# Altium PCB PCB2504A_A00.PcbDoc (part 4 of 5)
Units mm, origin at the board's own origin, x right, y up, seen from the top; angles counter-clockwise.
Board outline 115 x 60 mm, 6 copper layers (Top Layer, Signal Layer 2, Signal Layer 3, Signal Layer 4, Signal Layer 5, Bottom Layer), stack 1.555 mm thick; 403 components, 294 nets, 1344 pads, 774 vias.
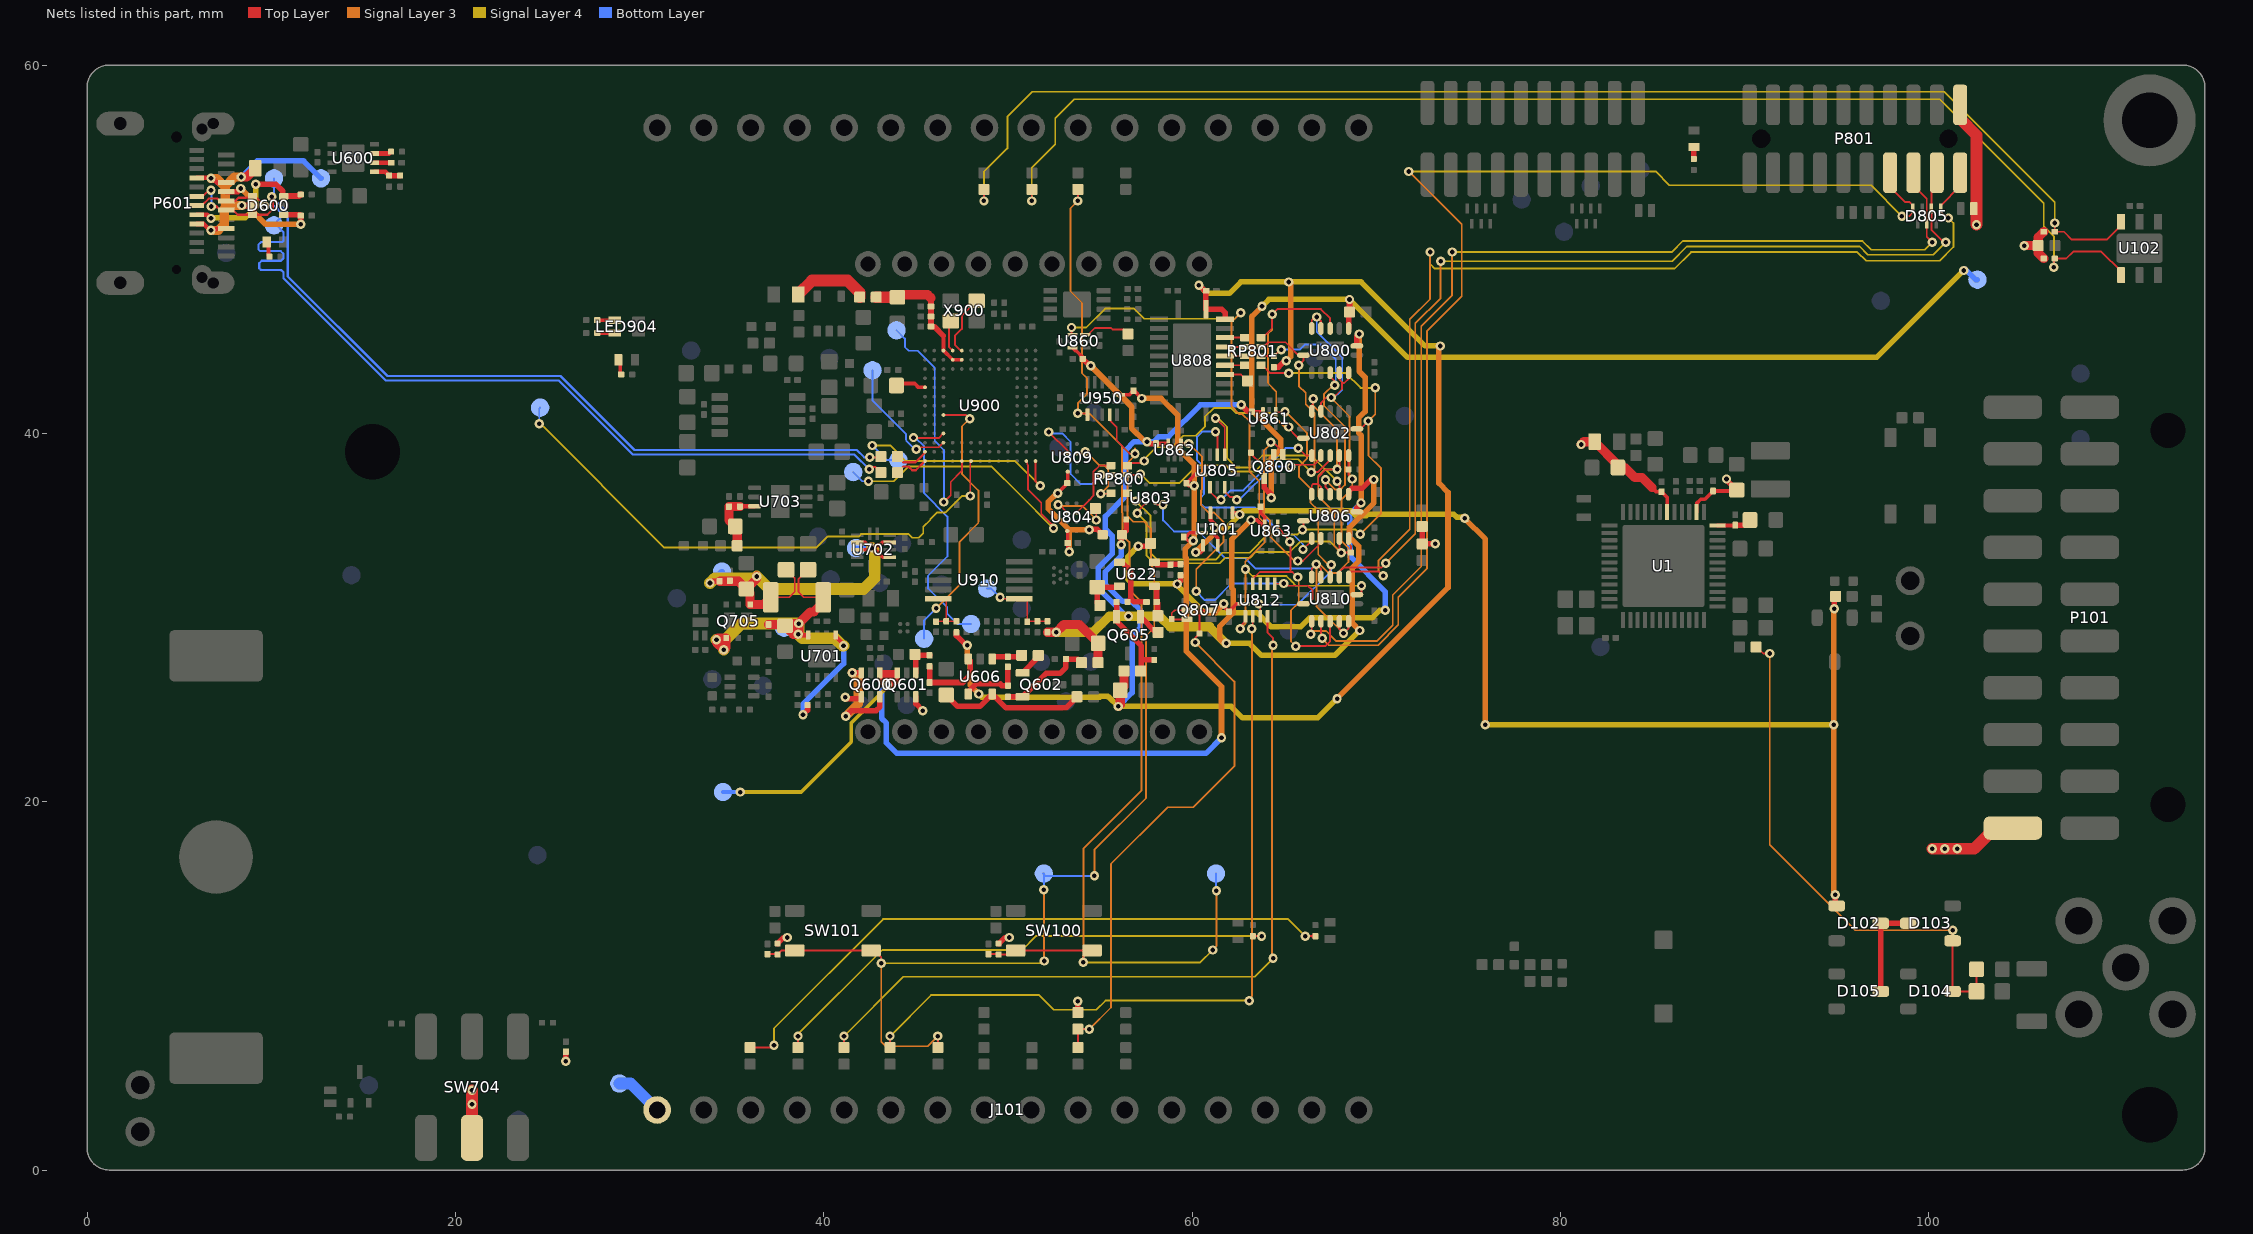
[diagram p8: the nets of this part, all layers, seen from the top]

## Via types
v1: diameter 0.508, hole 0.25, Top Layer to Bottom Layer, tented both sides, 774 vias

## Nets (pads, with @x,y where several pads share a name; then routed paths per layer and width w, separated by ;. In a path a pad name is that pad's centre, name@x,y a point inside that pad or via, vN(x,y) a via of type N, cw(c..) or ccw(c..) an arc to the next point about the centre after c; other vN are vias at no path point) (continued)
N16846192: R808.2 U802.6 U802.12 U803.C1 U806.5 U806.6 U806.12 U806.13 | length 31.6
  Top Layer w0.1: v1(57.025,35.675) 57.025,35.75 U803.C1@57.5,36.225 ; U806.6@66.5,36.7 66.5,37.175 66.575,37.25 66.85,37.25 ; U802.6@66.5,41.2 66.5,41.475 66.475,41.5 66.575,41.6 v1(66.575,41.875) ; U806.5@67,36.7 67,37.1 66.85,37.25 ; v1@68,33.6 U806.12@68,34.3 ; U802.12@68,38.8 68,38.175 v1(67.875,38.05) 67.269,38.05 66.85,37.631 66.85,37.25 ; v1(68.1,33.525) R808.2@68.625,33.525 68.625,33.9 68.5,34.025 U806.13@68.5,34.3
  Signal Layer 3 w0.1: v1(66.575,41.875) 66.575,41.5 67.875,40.2 v1(67.875,38.05) 67.2,38.05 66.85,37.7 66.85,36.6 67.725,35.725 67.725,33.9 v1(68.1,33.525)
  Signal Layer 4 w0.1: v1(57.025,35.675) 57.525,35.175 57.525,33.375 57.95,32.95 61.5,32.95 61.8,33.25 63.15,33.25 63.463,33.563 65.313,33.563 65.875,34.125 67.5,34.125 v1(68.1,33.525)
N16846231: C804.1 C810.1 L801.2 U804.A2 U809.A2 | length 8.5
  Top Layer w0.2: v1(52.7,36.75) 53.225,37.275 C810.1@53.225,37.3 53.25,37.325 U809.A2@53.25,37.925 ; U804.A2@53.225,34.7 53.25,34.675 C804.1@53.25,34.05 53.25,33.65 v1(53.325,33.575)
  Top Layer w0.3: v1(54.428,34.777) 54.404,34.8 54.85,34.8 L801.2@55.15,34.5
  Signal Layer 3 w0.3: v1(52.7,36.75) 52.653,36.75 52.2,36.297 52.2,35.902 53.325,34.777 ; v1(53.325,33.575) 53.325,34.777 ; v1(54.428,34.777) 53.325,34.777
N16846319: Q800.1 U806.10 | length 10.4
  Top Layer w0.1: v1(64.275,39.525) 64.4,39.525 64.925,39 Q800.1@64.925,38.85 ; v1(65.75,33.075) 66.025,33.075 67,34.05 U806.10@67,34.3
  Signal Layer 3 w0.1: v1(64.275,39.525) 64.275,39.425 63.9,39.05 63.9,35.6 64.237,35.262 64.237,34.588 64.237,34.393 65.556,33.075 v1(65.75,33.075)
N16846537: RP801.5 U808.21 | length 1.1
  Top Layer w0.1: U808.21@61.795,45.2 RP801.5@62.85,45.2
N16846539: RP801.6 U808.20 | length 1.1
  Top Layer w0.1: U808.20@61.795,44.7 RP801.6@62.85,44.7
N16846547: RP801.7 U808.19 | length 1.1
  Top Layer w0.1: U808.19@61.795,44.2 RP801.7@62.85,44.2
N16846551: RP801.8 U808.18 | length 1.1
  Top Layer w0.1: U808.18@61.795,43.7 RP801.8@62.85,43.7
N16846567: Q800.2 R815.1 | length 1.8
  Top Layer w0.1: R815.1@63.2,38.95 63.2,38.9 63.75,38.35 64.1,38.35 64.425,38.675 Q800.2@64.425,38.85
N16846723: R805.1 U808.17 | length 1.3
  Top Layer w0.1: U808.17@61.795,43.2 62.65,43.2 R805.1@63,42.85
N16846896: RP800.8 U809.C1 | length 4.1
  Top Layer w0.1: U809.C1@53.75,38.925 v1@54.175,38.925 ; v1(55.05,36.725) 55.575,36.725 RP800.8@55.6,36.75
  Signal Layer 3 w0.1: v1(54.2,39) 54.237,39 54.328,38.909 54.987,38.25 55.25,38.25 55.45,38.05 55.45,37.125 v1(55.05,36.725)
N16846900: RP800.6 U809.C2 | length 7.6
  Top Layer w0.1: v1(52.225,40.075) 53.25,39.05 U809.C2@53.25,38.925 ; v1(55.053,37.752) 54.952,37.752 54.95,37.75 55,37.75 RP800.6@55.6,37.75
  Bottom Layer w0.1: v1(52.225,40.075) 52.301,39.999 52.951,39.999 53.4,39.55 53.4,39.524 53.403,39.521 53.403,38.982 53.4,38.979 53.4,37.8 53.95,37.25 54.551,37.25 v1(55.053,37.752)
N16846924: RP800.5 U804.C1 | length 3.7
  Top Layer w0.1: U804.C1@53.725,35.7 54.407,36.382 54.413,36.382 54.643,36.612 54.643,36.618 54.643,37.918 54.975,38.25 RP800.5@55.6,38.25
N16847739: U805.10 U806.9 | length 13.8
  Top Layer w0.1: v1(61.275,40.1) 61.375,40 U805.10@61.375,38.855 ; v1(66.025,33.7) 66.5,34.175 U806.9@66.5,34.3
  Bottom Layer w0.1: v1(61.275,40.1) 60.55,40.1 60.275,39.825 60.275,38.55 60.65,38.175 60.65,36.7 60.492,36.542 60.492,36.169 60.675,35.986 61.139,35.986 62.43,35.986 62.437,35.993 62.763,35.993 62.77,35.986 63.414,35.986 64.882,34.518 65.482,34.518 66.025,33.975 v1(66.025,33.7)
N16847741: U805.9 U806.3 | length 12.5
  Top Layer w0.1: v1(61.275,40.825) 61.775,40.325 U805.9@61.775,38.855 ; v1(67.875,37.4) 68,37.275 U806.3@68,36.7
  Signal Layer 4 w0.1: v1(61.275,40.825) 61.425,40.825 61.9,40.35 61.9,38.65 62.4,38.15 63.175,38.15 63.825,38.8 66.481,38.8 67.875,37.406 v1(67.875,37.4)
N16847743: U802.10 U805.4 | length 6.7
  Top Layer w0.1: U805.4@61.775,37.085 61.775,36.825 62.05,36.55 62.275,36.55 v1(62.425,36.4) ; v1(65.375,38.2) 65.475,38.3 66.376,38.3 66.624,38.3 67,38.676 U802.10@67,38.8
  Bottom Layer w0.1: v1(62.425,36.4) 62.575,36.4 64.375,38.2 v1(65.375,38.2)
N16847749: U802.9 U805.2 | length 7.5
  Top Layer w0.1: U805.2@60.975,37.085 60.975,36.845 61.395,36.425 61.575,36.425 v1(61.575,36.391) ; v1@65.6,39.2 v1(65.775,39.2) 66.175,38.8 U802.9@66.5,38.8
  Bottom Layer w0.1: v1(61.575,36.391) 62.091,36.907 62.788,36.907 65.081,39.2 v1(65.775,39.2)
N16847975: R810.1 U804.C2 | length 3.8
  Top Layer w0.1: v1(52.725,36.125) 52.725,36.15 52.75,36.175 U804.C2@53.225,35.7 ; R810.1@54.75,35.925 54.8,35.875 v1(54.8,35.3)
  Signal Layer 3 w0.1: v1(52.725,36.125) 52.8,36.05 54.075,36.05 54.825,35.3 v1(54.8,35.3)
N16851386: C127.2 D103.1 D104.3 R128.2 R129.1 | length 28.9
  Top Layer w0.1: R129.1@90.675,28.4 91.025,28.05 v1(91.375,28.05) ; v1(101.3,13.025) D103.1@101.3,12.45 D104.3@101.3,9.7 R128.2@102.6,9.7 C127.2@102.6,10.9
  Signal Layer 3 w0.1: v1(91.375,28.05) 91.375,17.675 96.025,13.025 v1(101.3,13.025)
N16870930: D102.3 D103.3 D105.3 | length 5.2
  Top Layer w0.3: D105.3@97.4,9.7 D102.3@97.4,13.4 D103.3@98.9,13.4
N16916520: U810.1 U812.1 U860.4 | length 37.3
  Top Layer w0.1: v1(53.453,45.752) 53.453,45.397 U860.4@53.5,45.35 ; v1(62.625,29.4) 62.625,29.525 62.9,29.8 U812.1@62.9,30.065 ; U810.1@68.95,31.25 68.975,31.275 69.15,31.275 69.2,31.325 v1(69.2,31.725)
  Signal Layer 3 w0.1: v1(62.625,29.4) 62.9,29.675 v1(62.9,32.625) 62.887,32.637 62.887,33.038 63.95,34.1 63.95,35.125 63.65,35.425 63.65,37.4 63.125,37.925 63.125,40.65 62.725,41.05 62.575,41.05 62.15,41.475 62.15,46.05 v1(62.65,46.55)
  Signal Layer 4 w0.1: v1(53.453,45.752) 54.252,45.752 55.275,46.775 56.85,46.775 57.4,46.225 62.325,46.225 v1(62.65,46.55) ; v1(62.9,32.625) 63.268,32.257 65.124,32.257 65.407,31.974 65.407,31.962 65.637,31.732 65.649,31.732 65.656,31.725 v1(69.2,31.725)
N16916530: U810.4 U812.3 U861.4 | length 16.8
  Top Layer w0.1: v1(63.625,30.75) 63.7,30.675 U812.3@63.7,30.065 ; U861.4@64.55,41.15 65.025,41.15 v1(65.05,41.175) ; U810.4@67.5,32.2 67.5,32.775 67.55,32.825 v1(67.55,32.875)
  Signal Layer 3 w0.1: v1(65.05,41.175) 65.081,41.175 66.25,40.006 66.25,38.65 65.8,38.2 65.8,37.642 66.425,37.017 66.425,36.25 66.85,35.825 66.85,33.425 67.4,32.875 v1(67.55,32.875)
  Bottom Layer w0.1: v1(63.625,30.75) 63.675,30.7 65.725,30.7 67.55,32.525 v1(67.55,32.875)
N16916558: U810.11 U812.11 U863.4 | length 13
  Top Layer w0.1: U812.11@63.3,31.835 63.3,32.1 63.675,32.475 65.343,32.475 ; U863.4@64.65,35.05 64.65,34.925 64.9,34.675 64.9,34.6 65.3,34.2 v1(65.3,34.125) 65.343,34.082 65.343,32.475 ; v1(65.625,28.45) 67.225,28.45 67.5,28.725 U810.11@67.5,29.8 ; v1(65.75,32.2) 65.725,32.2 65.45,32.475 65.343,32.475
  Signal Layer 3 w0.1: v1(65.625,28.45) 65.375,28.7 65.375,30.389 65.793,30.807 65.793,32.118 65.75,32.161 v1(65.75,32.2)
N16916616: U810.8 U812.8 U862.4 | length 18.7
  Top Layer w0.1: U862.4@59.4,39.45 v1(59.825,39.45) ; U812.8@64.5,31.835 64.96,31.835 v1(64.975,31.85) 65.093,31.732 66.293,31.732 66.55,31.475 66.55,31.025 66.275,30.75 U810.8@66.05,30.75
  Signal Layer 3 w0.1: v1(59.825,39.45) 60.55,38.725 60.55,36.975 60.492,36.917 60.492,36.108 60.9,35.7 61.2,35.7 61.7,35.2 61.7,34.1 60.225,32.625 v1(60.225,31.425)
  Bottom Layer w0.1: v1(60.225,31.425) 60.7,30.95 61.225,30.95 62.125,31.85 v1(64.975,31.85)
N16917071: R882.1 U860.3 | length 2.6
  Top Layer w0.1: U860.3@54.2,45.35 54.35,45.35 54.725,45.725 55.612,45.725 55.687,45.65 56.275,45.65 R882.1@56.525,45.4
N16922979: R601.1 R602.2 U600.5 | length 1.5
  Top Layer w0.25: U600.5@15.6,54.2 16.2,54.2 R601.1@16.4,54
  Top Layer w0.3: R601.1@16.4,54 R602.2@17,54
N16923003: R600.1 U600.7 | length 0.9
  Top Layer w0.25: U600.7@15.6,55.2 16.4,55.2 R600.1@16.5,55.3
N16923019: C602.1 U600.6 | length 0.9
  Top Layer w0.25: U600.6@15.6,54.7 C602.1@16.525,54.7
N16923678: C620.1 R682.2 U606.4 | length 3.5
  Top Layer w0.3: U606.4@47.85,25.85 47.85,25.975 48.275,26.4 49.575,26.4 49.675,26.3 R682.2@50,26.3 C620.1@50,27.325
N16923728: Q601.4 R628.1 R672.2 | length 1.8
  Top Layer w0.3: R628.1@44.95,28 R628.1@45,27.95 ; Q601.4@45,27 R628.1@45,27.95 ; R672.2@45.75,27.95 R628.1@45,27.95
N16923751: C654.1 R689.2 U622.4 | length 3.5
  Top Layer w0.3: U622.4@56.05,33 56.2,33 56.675,32.525 56.675,31.025 ; R689.2@56.5,30.85 56.675,31.025 ; C654.1@57.525,30.85 56.85,30.85 56.675,31.025
N16923761: Q605.1 R686.2 | length 1.3
  Top Layer w0.3: Q605.1@57.2,30.05 58.05,29.2 R686.2@58.15,29.2
N16923771: C653.1 R629.1 U622.3 | length 1.5
  Top Layer w0.3: U622.3@57.95,33 58.075,32.875 C653.1@58.825,32.875 58.85,32.9 R629.1@59.375,32.9
N16923785: Q605.2 R687.1 R688.1 R689.1 | length 5.1
  Top Layer w0.3: R689.1@55.9,30.85 Q605.2@55.9,30.05 55.9,29.803 57.25,28.453 57.25,27.75 ; R687.1@57.2,27.1 57.25,27.15 57.25,27.75 ; R688.1@57.95,27.7 57.3,27.7 57.25,27.75
N16923803: C654.2 R686.1 U622.1 | length 1.7
  Top Layer w0.3: U622.1@57.95,31.7 58.075,31.575 C654.2@58.075,30.85 58.15,30.775 R686.1@58.15,30.1
N16923899: C652.1 R690.1 U622.5 | length 2.3
  Top Layer w0.3: R690.1@55,30.65 54.85,30.8 C652.1@54.85,31.65 56,31.65 U622.5@56.05,31.7
N16923917: C660.1 R681.1 U606.5 | length 8.2
  Top Layer w0.3: C660.1@46.65,25.8 47.275,25.175 48.475,25.175 U606.5@49.15,25.85 49.9,25.1 53.15,25.1 R681.1@53.75,25.7
N16923949: Q602.1 R679.2 | length 1.3
  Top Layer w0.3: Q602.1@50.8,27 51.65,27.85 R679.2@51.65,27.95
N16923963: C621.1 R672.1 U606.3 | length 4.2
  Top Layer w0.3: R672.1@45.75,27.35 C621.1@45.75,26.475 47.55,26.475 47.95,26.875 47.95,27.65 U606.3@47.85,27.75
N16923985: Q602.2 R674.1 R675.1 R682.1 | length 5.2
  Top Layer w0.3: R682.1@50,25.7 Q602.2@50.8,25.7 52.075,26.975 52.825,26.975 53.15,27.3 R674.1@53.15,27.75 53.8,27.75 R675.1@54,27.55
N16924018: C620.2 R679.1 U606.1 | length 1.7
  Top Layer w0.3: U606.1@49.15,27.75 49.275,27.875 C620.2@50,27.875 50.675,27.875 R679.1@50.75,27.95
N16924927: Q600.3 Q600.6 | length 5.9
  Top Layer w0.3: v1(41.2,24.65) 41.5,24.95 42.85,24.95 43.05,25.15 Q600.3@43.05,25.7 ; v1(41.55,27) Q600.6@42.05,27
  Signal Layer 3 w0.5: v1(41.2,24.65) 41.875,25.325 41.875,26.675 v1(41.55,27)
N16934878: C900.1 U900.J13 | length 1.7
  Top Layer w0.2: C900.1@43.95,42.6 44.057,42.707 44.939,42.707 45.146,42.5 U900.J13@45.5,42.5
N16934900: C903.1 C904.1 C905.1 C906.1 R130.2 U900.M9 U900.M10 U900.N11 | length 7.5
  Top Layer w0.2: 46.5,45.3 U900.N11@46.5,44.5 U900.M10@47,44 U900.M9@47.5,44
  Top Layer w0.3: 45.825,47.35 C906.1@45.825,46.9 C905.1@45.825,46.35 C904.1@45.825,45.8 46,45.8 46.5,45.3
  Top Layer w0.5: C903.1@44,47.4 44.125,47.525 45.65,47.525 45.825,47.35
  Top Layer w0.635: R130.2@42.85,47.4 C903.1@44,47.4
N16936696: U900.N10 X900.1 | length 1.7
  Top Layer w0.1: X900.1@46.9,46.1 46.8,46 46.8,44.7 U900.N10@47,44.5
N16936699: U900.N9 X900.3 | length 3.4
  Top Layer w0.1: U900.N9@47.5,44.5 47.45,44.5 47.125,44.825 47.125,45.3 47.5,45.675 47.5,46.4 X900.3@48.3,47.2
N16939106: TPJ909.1 U900.C11 | length 6.7
  Top Layer w0.1: v1@45.25,39.25 46.25,39.25 U900.C11@46.5,39.5
  Bottom Layer w0.1: TPJ909.1@42.651,43.427 42.651,41.774 44.475,39.95 44.475,39.656 44.482,39.649 44.482,39.612 44.944,39.15 v1(45.025,39.15)
N16939109: TPJ910.1 U900.D11 | length 14.5
  Top Layer w0.1: v1(44.875,39.775) 44.9,39.75 46.25,39.75 U900.D11@46.5,40
  Bottom Layer w0.1: v1(44.875,39.775) 44.975,39.775 45.45,39.3 45.45,36.75 46.718,35.482 46.718,33.318 45.662,32.263 45.662,31.588 46.7,30.55 46.7,30.2 47.25,29.65 TPJ910.1@48.003,29.65
N16939489: TPJ911.1 U900.F11 | length 15.2
  Top Layer w0.1: U900.F11@46.5,41 47.725,41 v1(47.925,40.8)
  Signal Layer 3 w0.1: v1(46.1,30.5) 47.375,31.775 47.375,34.119 48.393,35.137 48.393,35.193 48.4,35.2 48.4,36.9 47.5,37.8 47.5,40.375 v1(47.925,40.8)
  Bottom Layer w0.1: TPJ911.1@45.453,28.85 45.453,29.853 v1(46.1,30.5)
N16939638: TPJ900.1 U900.A2 | length 17.1
  Top Layer w0.1: U900.A2@51,38.5 51.05,38.45 51.05,38.314 51.1,38.264 51.1,36.954 51.81,36.243 51.81,35.64 52.475,34.975 v1(52.475,34.85)
  Signal Layer 4 w0.1: v1(42.429,37.4) 43.8,37.4 44.6,38.2 49.125,38.2 50.55,36.775 v1(52.475,34.85)
  Bottom Layer w0.1: TPJ900.1@41.602,37.9 42.102,37.4 v1(42.429,37.4)
N16939640: TPJ901.1 U900.A1 | length 13.6
  Top Layer w0.1: U900.A1@51.5,38.5 51.5,37.375 51.737,37.137 51.8,37.075 51.875,37.15 v1(51.75,37.15)
  Signal Layer 4 w0.1: v1(42.631,39.346) 43.604,39.346 44.45,38.5 50.4,38.5 v1(51.75,37.15)
  Bottom Layer w0.1: v1(42.631,39.346) 43.426,38.55 TPJ901.1@44.053,38.55
N16940103: TPJ908.1 U900.A9 | length 13.3
  Top Layer w0.1: v1(46.525,36.275) 46.9,36.65 46.9,37.362 47.5,37.962 U900.A9@47.5,38.5
  Bottom Layer w0.1: TPJ908.1@43.952,45.601 44.407,45.146 44.407,44.693 44.607,44.493 45.107,44.493 46.025,43.575 46.025,39.6 46.525,39.1 v1(46.525,36.275)
N16942491: R902.2 U900.B13 | length 1.9
  Top Layer w0.12: R902.2@44,38.75 44.32,38.43 44.98,38.43 45.5,38.95 U900.B13@45.5,39
N16942503: R904.2 U900.A13 | length 1.9
  Top Layer w0.12: R904.2@44,37.875 44.325,38.2 44.6,38.2 44.8,38 45,38 U900.A13@45.5,38.5
N16943456: TPJ902.1 U900.A8 | length 30.7
  Top Layer w0.1: v1(47.95,36.6) 47.957,36.607 47.957,38.457 U900.A8@48,38.5
  Signal Layer 4 w0.1: v1(24.551,40.527) v1(24.551,40.527) 24.55,40.6 31.35,33.8 39.6,33.8 40.2,34.4 41.9,34.4 42.032,34.532 44.468,34.532 ; 44.513,34.532 44.468,34.532 ; v1(47.95,36.6) 47.5,36.6 46.6,35.7 46.144,35.7 45.782,35.338 45.782,35.3 45.407,34.925 45.407,34.571 45.168,34.332 44.812,34.332 44.612,34.532 44.468,34.532
  Bottom Layer w0.1: v1(24.551,40.527) 24.551,41.351 TPJ902.1@24.6,41.4
N16944010: LED903.2 R912.2 | length 0.9
  Top Layer w0.2: LED903.2@28.85,44 28.95,43.9 28.95,43.25 R912.2@29,43.2
N16966205: LED904.2 R920.2 | length 0.9
  Top Layer w0.2: R920.2@27.7,46.15 LED904.2@28.65,46.15
N16966207: LED904.1 R919.2 | length 0.9
  Top Layer w0.2: R919.2@27.7,45.45 LED904.1@28.65,45.45
N16966211: LED901.1 R903.2 | length 0.9
  Top Layer w0.2: LED901.1@9.75,50.4 9.85,50.3 9.85,49.65 R903.2@9.9,49.6
N16966215: LED900.1 R900.2 | length 0.7
  Top Layer w0.3: R900.2@87.25,54.9 LED900.1@87.25,55.55
N16996446: Q807.5 Q807.6 R838.1 | length 2
  Top Layer w0.1: Q807.6@59.725,29.9 58.925,29.9 R838.1@58.9,29.925 58.9,30.25 59.05,30.4 Q807.5@59.725,30.4
N17012885: L900.2 R130.1 | length 4.2
  Top Layer w0.635: L900.2@38.615,47.55 39.365,48.3 41.3,48.3 41.95,47.65 R130.1@41.95,47.4
N17065843: C15.1 C16.1 U1.36 | length 1.9
  Top Layer w0.2: U1.36@88.535,35 89.475,35 C15.1@89.5,35.025
  Top Layer w0.3: C15.1@89.5,35.025 90.025,35.025 C16.1@90.3,35.3
SENSOR_I2C_SCL: R109.2 R303.2 U102.6 | length 71.5
  Top Layer w0.1: v1(48.7,52.625) R303.2@48.7,53.25 ; v1(106.85,51.425) R109.2@106.85,50.95 107.35,50.95 107.775,50.525 109.675,50.525 110.45,51.3 U102.6@110.45,51.5
  Signal Layer 4 w0.1: v1(48.7,52.625) 48.7,54.2 49.975,55.475 49.975,57.2 51.325,58.55 100.85,58.55 106.85,52.55 v1(106.85,51.425)
SENSOR_I2C_SDA: R108.2 R302.2 U102.1 | length 70.7
  Top Layer w0.1: v1(51.3,52.625) R302.2@51.3,53.25 ; v1(106.8,49.025) 106.8,49.45 R108.2@106.85,49.5 107.475,49.5 107.85,49.875 109.375,49.875 110.45,48.8 U102.1@110.45,48.6
  Signal Layer 4 w0.1: v1(51.3,52.625) 51.3,54.425 52.575,55.7 52.575,57.125 53.6,58.15 100.6,58.15 106.25,52.5 106.25,51.25 106.8,50.7 v1(106.8,49.025)
SI_HEADER_ENABLE: R807.2 U800.5 U800.6 U800.12 U800.13 U802.5 U802.13 U803.C2 U810.5 U810.6 U810.12 U810.13 | length 42.2
  Top Layer w0.1: U803.C2@58,36.225 58.1,36.125 v1(58.425,36.125) ; U810.6@66.5,32.2 66.5,32.65 v1(66.75,32.9) 67,32.65 U810.5@67,32.2 ; U800.6@66.5,45.7 66.5,46.15 66.675,46.325 v1(66.775,46.325) 67,46.1 U800.5@67,45.7 ; U802.5@67,41.2 67,41.65 67.3,41.95 v1(67.55,41.95) 67.55,41.881 67.581,41.85 68.143,42.412 68.143,42.738 ; U810.12@68,29.8 68,29.375 v1(68.225,29.15) 68.5,29.425 U810.13@68.5,29.8 ; U800.12@68,43.3 68,42.931 68.143,42.788 68.143,42.738 ; U802.13@68.5,38.8 R807.2@68.5,38.05 68.5,37.725 v1(68.7,37.525) ; U800.13@68.5,43.3 68.5,42.975 68.263,42.738 68.143,42.738
  Signal Layer 3 w0.1: v1(67.55,41.95) 67.525,41.95 68.55,40.925 68.55,37.675 v1(68.7,37.525) 68.7,37 68.125,36.425 68.125,34.15 68.493,33.782 68.493,33.018 67.9,32.425 67.4,32.425 66.925,32.9 v1(66.75,32.9) 66.75,30.625 v1(68.225,29.15)
  Bottom Layer w0.1: v1(58.425,36.125) 58.425,35.275 59.025,34.675 60.35,34.675 61.8,33.225 62.9,33.225 63.462,32.663 66.513,32.663 v1(66.75,32.9) ; v1(66.775,46.325) 66.775,45.525 68.157,44.143 68.157,42.382 v1@67.625,41.85
SI_VCOM_CTS: D805.4 P801.8 U810.10 | length 64.2
  Top Layer w0.1: U810.10@67,29.8 67,28.95 v1(67.075,28.875) ; P801.8@97.905,54.158 97.905,53.37 98.7,52.575 98.95,52.575 99.15,52.375 D805.4@99.15,52.215 99.15,52 98.95,51.8 v1(98.55,51.8)
  Signal Layer 3 w0.1: v1(67.075,28.875) 67.075,28.85 67.425,28.5 70.1,28.5 71.2,29.6 71.2,31.1 72.75,32.65 72.75,45.55 74.65,47.45 74.65,51.35 v1(71.775,54.225)
  Signal Layer 4 w0.1: v1(71.775,54.225) 85.175,54.225 85.925,53.475 96.875,53.475 v1(98.55,51.8)
SI_VCOM_RTS: D805.6 P801.6 U810.9 | length 58.3
  Top Layer w0.1: v1(66.45,29.1) 66.5,29.15 U810.9@66.5,29.8 ; P801.6@99.175,54.158 99.175,53.475 99.9,52.75 D805.6@99.9,51.385 99.9,50.675 v1(100.2,50.375)
  Signal Layer 3 w0.1: v1(66.45,29.1) 66.625,29.275 67.275,29.275 67.825,28.725 70.042,28.725 70.9,29.583 70.9,31.225 72.45,32.775 72.45,45.825 74.125,47.5 v1(74.125,49.85)
  Signal Layer 4 w0.1: v1(74.125,49.85) 86.05,49.85 86.65,50.45 96.4,50.45 96.875,49.975 99.8,49.975 v1(100.2,50.375)
SI_VCOM_RXD: D805.1 P801.2 U810.2 | length 55.9
  Top Layer w0.1: U810.2@68.5,32.2 68.5,32.4 68.6,32.5 70.15,32.5 v1(70.375,32.275) ; v1(101.075,51.7) 101,51.7 100.65,52.05 D805.1@100.65,52.215 100.65,52.375 101.715,53.44 P801.2@101.715,54.158
  Signal Layer 3 w0.1: v1(70.375,32.275) 70.132,32.518 70.132,33.113 71.825,34.806 71.825,46.2 72.925,47.3 v1(72.925,49.85)
  Signal Layer 4 w0.1: v1(72.925,49.85) 72.925,49.2 73.175,48.95 86.2,48.95 87.1,49.85 96.125,49.85 96.6,49.375 100.6,49.375 101.35,50.125 101.35,51.425 v1(101.075,51.7)
SI_VCOM_TXD: D805.2 P801.4 U810.3 | length 53.1
  Top Layer w0.1: U810.3@68,32.2 68,32.475 68.238,32.713 70.288,32.713 v1(70.525,32.95) ; P801.4@100.445,54.158 100.15,53.863 D805.2@100.15,52.215 100.15,51.05 100.825,50.375 v1(100.925,50.375)
  Signal Layer 3 w0.1: v1(70.525,32.95) 72.125,34.55 72.125,45.975 73.5,47.35 v1(73.5,49.35)
  Signal Layer 4 w0.1: v1(73.5,49.35) 86.075,49.35 86.875,50.15 96.25,50.15 96.7,49.7 100.25,49.7 v1(100.925,50.375)
TCK_SWCLK: RP800.3 RP801.3 U800.8 U802.11 | length 22.5
  Top Layer w0.1: RP800.3@56.5,37.75 57.15,37.75 v1(57.2,37.8) ; RP801.3@63.75,44.7 63.889,44.7 64.139,44.95 65.075,44.95 65.775,44.25 U800.8@66.05,44.25 66.05,43.95 v1(65.803,43.702) ; v1(66.475,37.9) 66.824,37.9 67.5,38.576 U802.11@67.5,38.8
  Signal Layer 3 w0.1: v1@65.825,43.724 v1(65.803,43.702) 65.803,42.572 66.175,42.2 66.175,41.575 66.65,41.1 66.65,38.075 v1(66.475,37.9)
  Signal Layer 4 w0.1: v1@57.3,37.8 v1(57.2,37.8) 57.7,37.3 59.3,37.3 60.271,38.271 61.829,38.271 62.175,37.925 63.4,37.925 64.075,38.6 65.775,38.6 v1(66.475,37.9)
TDI: RP800.1 RP801.1 U802.1 U806.8 | length 33
  Top Layer w0.1: RP800.1@56.5,36.75 56.85,36.4 v1@56.95,36.4 ; v1(56.953,36.327) 56.95,36.33 v1@56.95,36.4 ; v1@57,36.4 v1@56.95,36.4 ; RP801.1@63.75,43.7 63.827,43.7 64.252,43.275 v1(65.25,43.275) ; v1@66.05,34.875 U806.8@66.05,35.25 ; U802.1@68.95,40.25 69.15,40.25 v1(69.575,40.675)
  Signal Layer 3 w0.1: v1(69.128,34.527) 70.268,35.666 70.268,38.107 69.575,38.8 v1(69.575,40.675) 69.95,41.05 v1(69.95,42.475)
  Signal Layer 4 w0.1: v1(56.953,36.327) 57.749,35.53 57.749,33.501 58.1,33.15 61.278,33.15 61.65,33.522 63.122,33.522 64.118,34.518 65.743,34.518 v1(66,34.775) 68.88,34.775 v1(69.128,34.527) 69.128,34.528 v1@69.2,34.6 ; v1(65.25,43.275) 68.35,43.275 69.15,42.475 v1(69.95,42.475)
TDO_SWO: R801.1 RP801.2 U800.11 U806.4 | length 15.3
  Top Layer w0.1: RP801.2@63.75,44.2 R801.1@64.45,44.2 64.775,44.525 64.825,44.525 v1(64.85,44.55) ; v1(67.25,37.475) 67.25,37.074 67.5,36.824 U806.4@67.5,36.7 ; U800.11@67.5,43.3 67.5,43.075 67.75,42.825 v1(67.75,42.625)
  Signal Layer 3 w0.1: v1(67.25,37.475) 67.25,37.469 67.769,36.95 68.05,36.95 68.3,37.2 68.3,40.375 67.157,41.518 67.157,42.126 67.656,42.625 v1(67.75,42.625)
  Bottom Layer w0.1: v1(64.85,44.55) 65.85,44.55 66.125,44.825 67,44.825 67.8,44.025 67.8,42.65 67.775,42.625 v1(67.75,42.625)
TMS_SWDIO: RP800.4 RP801.4 U800.4 U802.8 | length 24.5
  Top Layer w0.1: RP800.4@56.5,38.25 56.55,38.25 56.7,38.4 56.9,38.4 57.2,38.4 57.3,38.5 v1(57.4,38.5) ; RP801.4@63.75,45.2 63.825,45.2 64.35,45.725 v1(64.35,46.475) 64.625,46.75 67,46.75 67.5,46.25 U800.4@67.5,45.7 ; v1(65.25,40.35) 65.175,40.35 65.775,39.75 U802.8@66.05,39.75
  Signal Layer 3 w0.1: v1(64.35,46.475) 64.35,45.625 64.125,45.4 64.125,42.725 64.575,42.275 64.575,40.8 65.1,40.275 65.175,40.35 v1(65.25,40.35)
  Signal Layer 4 w0.1: v1(57.4,38.5) 57.4,38.6 58.05,39.25 58.9,39.25 59.525,39.875 60.206,39.875 60.7,40.369 60.7,40.9 61.175,41.375 62.125,41.375 62.4,41.1 64.275,41.1 65.05,40.325 65.075,40.35 v1(65.25,40.35)
UIF_BUTTON0: C102.1 R100.1 R301.2 SW100.3 SW100.4 TPJ652.1 U950.8 | length 64.4
  Top Layer w0.1: C102.1@48.95,11.725 49.475,11.725 R100.1@49.5,11.7 50.2,11.7 SW100.3@50.425,11.925 SW100.4@54.35,11.925 ; v1(53.8,41.088) 54.253,41.088 U950.8@54.325,41.015 ; v1(53.8,52.625) R301.2@53.8,53.25 ; v1(54.1,11.275) 54.1,11.675 SW100.4@54.35,11.925 ; SW100.4@54.575,11.925 SW100.4@54.35,11.925
  Signal Layer 3 w0.1: v1(53.8,52.625) 53.4,52.225 53.4,47.725 54.025,47.1 54.025,43.275 54.3,43 54.3,42.15 53.8,41.65 v1(53.8,41.088) 54.412,41.088 56.2,39.3 56.2,35.7 56.218,35.682 56.218,34.482 56.6,34.1 56.6,31.5 57.25,30.85 57.25,20.6 54.1,17.45 v1(54.1,11.275) ; v1(61.125,11.95) 61.325,12.15 v1(61.325,15.175)
  Signal Layer 4 w0.1: v1(54.1,11.275) 60.45,11.275 v1(61.125,11.95)
  Bottom Layer w0.1: TPJ652.1@61.303,16.102 61.303,15.197 v1(61.325,15.175)
UIF_BUTTON1: C103.1 R101.1 R308.2 SW101.3 SW101.4 TPJ653.1 U950.11 | length 60.1
  Top Layer w0.1: C103.1@36.95,11.725 37.475,11.725 R101.1@37.5,11.7 37.725,11.925 SW101.3@38.425,11.925 SW101.4@42.575,11.925 42.75,11.925 43.125,11.55 v1(43.125,11.225) ; R308.2@46.2,6.65 v1@46.2,7.275 ; U950.11@55.525,41.015 55.525,40.725 55.91,40.34 55.91,39.615 56.625,38.9 v1(56.9,38.9)
  Signal Layer 3 w0.1: v1(43.125,11.225) 43.125,6.975 43.375,6.725 45.65,6.725 v1(46.2,7.275) ; v1(51.953,15.226) 51.953,11.372 v1(51.975,11.35) ; v1(54.7,15.975) 54.7,17.4 57.5,20.2 57.5,29 57.95,29.45 57.95,32.65 57.769,32.831 57.769,34.831 57.4,35.2 56.8,35.2 56.5,35.5 56.5,38.4 56.9,38.8 v1(56.9,38.9) 56.9,39.189
  Signal Layer 4 w0.1: v1(43.125,11.225) 51.85,11.225 v1(51.975,11.35)
  Bottom Layer w0.1: v1(51.953,15.226) 51.95,15.228 51.95,15.275 51.953,15.278 TPJ653.1@51.953,16.051 ; v1(54.7,15.975) 52.029,15.975 TPJ653.1@51.953,16.051 ; TPJ653.1@51.953,16.051 51.902,16.102 TPJ653.1@51.953,16.102 TPJ653.1@51.953,16.051
UIF_LED0: R106.2 R314.2 | length 34.5
  Top Layer w0.1: R314.2@36,6.65 37.175,6.65 v1(37.3,6.775) ; v1(66.15,12.7) R106.2@66.65,12.7
  Top Layer w0.3: R106.2@66.65,12.7 R106.2@66.7,12.7
  Signal Layer 4 w0.1: v1(37.3,6.775) 37.3,7.7 43.225,13.625 65.225,13.625 v1(66.15,12.7)
UIF_LED1: R107.2 R315.2 | length 28.6
  Top Layer w0.1: R315.2@38.6,6.65 v1(38.6,7.275) ; R107.2@63.3,12.7 v1(63.775,12.7)
  Signal Layer 4 w0.1: v1(38.6,7.275) 38.6,7.375 43.175,11.95 50.775,11.95 51.525,12.7 v1(63.775,12.7)
USB_DM: D600.6 P601.A7 P601.B7 R902.1 TPJ612.1 | length 48.1
  Top Layer w0.12: P601.B7@5.95,52.875 6.275,52.875 6.6,53.2 v1(6.725,53.2) ; v1@6.75,52.35 7,52.35 7.225,52.125 P601.A7@7.55,52.125 7.925,52.125 8.175,51.875 D600.6@8.975,51.875 9.778,51.875 10.075,52.172 10.075,52.8 v1(10.025,52.85) ; v1(42.5,38.7) 43.05,38.7 R902.1@43.1,38.75
  Bottom Layer w0.12: v1@6.725,53.15 6.75,53.125 v1@6.75,52.35 ; TPJ612.1@10.15,53.85 10.15,52.975 v1(10.025,52.85) 10.9,51.975 10.9,48.525 16.31,43.115 25.71,43.115 27.55,41.275 29.725,39.1 41.8,39.1 42.2,38.7 v1(42.5,38.7)
  other v1: 6.75,52.325
USB_DP: D600.4 P601.A6 P601.B6 R904.1 TPJ611.1 | length 51.1
  Top Layer w0.12: P601.B6@5.95,52.375 6.225,52.375 6.6,52.75 7.075,52.75 7.2,52.625 P601.A6@7.55,52.625 8.05,52.625 8.225,52.8 8.775,52.8 8.85,52.875 D600.4@8.975,52.875 9.138,52.875 9.65,52.363 v1(9.65,52.35) ; v1(42.475,38.05) 42.475,38.173 42.477,38.175 42.8,38.175 R904.1@43.1,37.875
  Bottom Layer w0.12: v1(9.65,52.35) 10.175,52.35 10.55,51.975 10.55,51.762 10.15,51.362 TPJ611.1@10.15,51.3 10.291,51.3 10.66,50.931 10.66,50.47 10.59,50.4 9.45,50.4 9.3,50.25 9.3,49.997 9.397,49.9 10.516,49.9 10.66,49.756 10.66,49.51 10.525,49.375 9.475,49.375 9.347,49.247 9.347,48.967 9.438,48.875 10.53,48.875 10.66,48.745 10.66,48.426 16.211,42.875 25.611,42.875 27.38,41.105 29.626,38.86 41.665,38.86 v1(42.475,38.05)
USBC_CC1: D600.1 P601.A5 R621.2 | length 6.7
  Top Layer w0.3: P601.A5@7.55,53.125 8.175,53.125 v1(8.35,53.3) ; D600.1@10.675,51.875 11.55,51.875 R621.2@11.6,51.825 v1(11.6,51.35)
  Signal Layer 3 w0.3: v1(8.35,53.3) 8.975,52.675 8.975,52.075 9.7,51.35 v1(11.6,51.35)
USBC_CC2: D600.3 P601.B5 R620.2 | length 7.7
  Top Layer w0.25: P601.B5@5.95,51.875 6.525,51.875 6.7,51.7 v1@6.725,51.7
  Top Layer w0.3: v1(9.15,53.525) 10.25,53.525 10.625,53.15 10.625,52.925 D600.3@10.675,52.875 10.693,52.893 11.5,52.893 11.5,52.875 R620.2@11.6,52.975
  Signal Layer 4 w0.3: v1@6.725,51.7 8.575,51.7 9.15,52.275 v1(9.15,53.525)
  other v1: 6.725,51.675
USBC_VBUS: D600.5 L600.1 P601.A4 P601.A9 P601.B4 P601.B9 TPJ613.1 | length 16.1
  Top Layer w0.25: P601.B4@5.95,51.375 6.323,51.375 6.725,50.973 v1(6.725,51.025) 6.725,51.05 6.925,51.05 7,51.125 P601.A9@7.55,51.125 ; P601.B9@5.95,53.875 6.7,53.875 v1(6.725,53.85) 6.825,53.85 7.05,53.625 P601.A4@7.55,53.625
  Top Layer w0.35: v1(8.4,52.375) D600.5@8.975,52.375
  Top Layer w0.5: v1(8.375,53.925) 8.66,53.925 L600.1@9.135,54.4
  Signal Layer 3 w0.5: v1(6.725,51.025) 7.125,51.025 7.45,51.35 7.45,52.2 7.625,52.375 ; v1(6.725,53.85) 7.025,53.85 7.5,53.375 ; v1(8.375,53.925) 8,53.925 7.5,53.425 7.5,53.375 ; v1(8.4,52.375) 7.625,52.375 ; 7.5,53.375 7.5,52.5 7.625,52.375
  Bottom Layer w0.3: v1(8.375,53.925) 9.25,54.8 11.75,54.8 TPJ613.1@12.7,53.85
V_ADC: D102.1 R114.2 U101.1 U101.3 U101.8 U101.11 | length 66.7
  Top Layer w0.2: v1(60.2,33.55) 60.45,33.55 60.475,33.525 60.6,33.65 U101.1@60.6,33.915 ; U101.11@61,35.685 61,35.3 61.225,35.075 v1(61.225,34.875) 61.225,34.5 61.4,34.325 U101.3@61.4,33.915 ; U101.8@62.2,35.685 62.49,35.685 62.6,35.575 v1(62.6,35.6)
  Top Layer w0.3: v1(94.875,30.475) 94.875,31.075 R114.2@94.95,31.15 ; v1(94.925,14.95) 94.925,14.425 D102.1@95,14.35
  Signal Layer 3 w0.3: v1(60.2,33.55) 61.225,34.575 v1(61.225,34.875) ; v1(74.8,35.388) 75.925,34.262 v1(75.925,24.175) ; v1(94.875,30.475) 94.85,30.45 v1(94.85,24.175) 94.85,15.025 v1(94.925,14.95)
  Signal Layer 4 w0.3: v1(61.225,34.875) 61.875,34.875 v1(62.6,35.6) 62.605,35.6 62.805,35.8 68.62,35.8 68.888,35.532 69.462,35.532 69.535,35.605 74.22,35.605 74.375,35.45 74.738,35.45 v1(74.8,35.388) ; v1(75.925,24.175) v1(94.85,24.175)
  Bottom Layer w0.3: v1@61.125,34.875 v1(61.225,34.875)
V_SW: C113.1 C800.1 C828.1 C950.1 Q600.4 Q601.6 TPJ608.1 U101.14 U805.14 U812.14 U950.14 | length 69
  Top Layer w0.2: U950.14@56.01,42.1 56.6,42.1 C950.1@56.825,42.325 56.85,42.325 v1(57.275,41.9) ; C113.1@59.55,34.375 59.599,34.375 59.799,34.175 v1(60.075,34.175) ; C113.1@59.65,34.375 59.875,34.6 U101.14@60.515,34.6 ; v1(60.121,37.15) 60.15,37.15 60.125,37.175 59.825,37.175 C800.1@59.7,37.3 60.17,37.77 U805.14@60.49,37.77 ; v1(61.725,30.75) 61.725,30.6 C828.1@62,30.325 62.425,30.75 U812.14@62.815,30.75
  Top Layer w0.3: 43.05,26.6 43.882,26.6 43.941,26.541 ; 43.05,26.6 Q600.4@43.05,26.75 ; 43.05,26.6 43.3,26.35 v1(43.45,26.35) 43.75,26.35 43.941,26.541 ; Q600.4@43.05,26.75 Q601.6@44,26.75 ; Q600.4@43.05,26.75 Q600.4@43.05,27 Q601.6@44,27 Q601.6@44,26.75 ; 43.941,26.541 44,26.6 Q601.6@44,26.75
  Signal Layer 3 w0.3: v1(57.275,41.9) 58.325,41.9 59.225,41 59.225,39.2 ; 59.225,39.325 59.225,39.2 ; v1(61.6,23.475) 61.6,26.25 59.675,28.175 59.675,30.032 ; v1(61.725,30.75) 61.25,30.275 59.693,30.275 ; 59.225,39.2 60.121,38.304 v1(60.121,37.15) 60.121,34.221 v1(60.075,34.175) 59.625,33.725 59.625,33.3 59.693,33.232 59.693,30.275 ; 59.675,30.032 59.675,30.275 59.693,30.275 ; 59.675,30.032 59.693,30.05 59.693,30.275
  Signal Layer 4 w0.2: v1(35.475,20.525) 38.775,20.525 41.5,23.25 41.5,24.275 43.45,26.225 v1(43.45,26.35) v1@43.425,26.35
  Bottom Layer w0.2: TPJ608.1@34.528,20.527 34.53,20.525 v1(35.475,20.525)
  Bottom Layer w0.3: v1(43.45,26.35) 43.15,26.05 43.15,24.525 43.4,24.275 43.4,23.2 43.975,22.625 60.75,22.625 v1(61.6,23.475)
VCOM_CTS: U812.9
VCOM_ENABLE: Q807.2 R305.2 R320.1 R839.2 | length 30
  Top Layer w0.1: R305.2@53.8,6.65 R320.1@53.8,7.65 v1(54.425,7.65) ; v1(60.175,28.65) 60.175,28.9 R839.2@60.4,29.125 60.4,30.3 60.5,30.4 Q807.2@61.025,30.4
  Signal Layer 3 w0.1: v1(54.425,7.65) 55.6,8.825 55.6,16.625 58.675,19.7 60.075,19.7 62.3,21.925 62.3,26.525 v1(60.175,28.65)
VCOM_RTS: U812.10
VCOM_RX: R310.2 U812.4 | length 44.4
  Top Layer w0.1: R310.2@41.1,6.65 v1(41.1,7.275) ; U812.4@64.1,30.065 64.1,29.65 64.1,29.176 64.4,28.876 v1(64.4,28.5)
  Signal Layer 3 w0.1: v1(64.4,11.5) 64.35,11.55 64.35,28.45 v1(64.4,28.5)
  Signal Layer 4 w0.1: v1(41.1,7.275) 44.325,10.5 63.4,10.5 v1(64.4,11.5)
VCOM_TX: R309.2 U812.2 | length 42.6
  Top Layer w0.1: R309.2@43.6,6.65 v1(43.6,7.275) ; v1(63.25,29.4) 63.225,29.4 63.3,29.475 U812.2@63.3,30.065
  Signal Layer 3 w0.1: v1(63.1,9.2) 63.1,9.3 63.25,9.45 63.25,15.75 v1(63.25,29.4)
  Signal Layer 4 w0.1: v1(43.6,7.275) 45.825,9.5 51.7,9.5 52.5,8.7 54.8,8.7 55.3,9.2 v1(63.1,9.2)
VCS: C710.1 C714.1 C728.1 R717.2 U703.7 | length 3.7
  Top Layer w0.25: C710.1@35.475,36.05 U703.7@36.25,36.05
  Top Layer w0.3: C710.1@35.45,36.025 C710.1@35.475,36.05
  Top Layer w0.5: R717.2@35.3,33.9 35.3,34.85 C714.1@35.2,34.95 34.85,35.3 C728.1@34.85,36.025 C710.1@35.45,36.025
VMCU: C5.1 C6.1 C9.1 C10.1 C706.1 D808.1 J101.1 L1.1 P101.2 P801.1 Q600.1 Q601.3 R100.2 R101.2 R108.1 R109.1 R111.1 R118.1 R150.2 R320.2 SW704.5 TP703.1 U1.38 U1.42 | length 36.4
  Top Layer w0.2: 84.983,37.058 85.216,36.825 C6.1@85.5,36.825 85.8,36.525 U1.42@85.8,35.735 ; U1.38@87.4,35.735 87.4,36.2 87.625,36.425 87.85,36.425 C9.1@88.3,36.875 89.555,36.875 C10.1@89.575,36.895
  Top Layer w0.3: v1(26,5.9) 26,5.925 C706.1@26,6.425 ; R101.2@37.5,12.3 37.825,12.625 v1(38.025,12.625) ; v1(41.177,25.676) 41.177,25.673 41.25,25.6 41.95,25.6 Q600.1@42.05,25.7 ; Q601.3@45,25.7 45,25.325 v1(45.375,24.95) ; R100.2@49.5,12.3 49.525,12.3 49.85,12.625 v1(50.075,12.625) ; R320.2@53.8,8.55 v1(53.8,9.175) ; R111.1@72.5,34.95 R118.1@72.5,34 v1@73,34 ; v1(73.2,34) v1@73,34 ; v1@73.3,34 v1@73,34 ; v1(89.025,37.525) 89.025,37.475 C10.1@89.575,36.925
  Top Layer w0.5: v1(81.125,39.4) 81.275,39.55 L1.1@81.86,39.55 83.125,38.285 C5.1@83.125,38.15 83.5,38.15 84.05,37.6 84.441,37.6 84.983,37.058 ; C10.1@89.575,36.895 C10.1@89.575,36.925 ; v1(105.2,50.2) R150.2@105.95,50.2 ; R108.1@106.25,49.5 105.95,49.8 R150.2@105.95,50.2 ; R109.1@106.25,50.95 105.95,50.65 R150.2@105.95,50.2
  Top Layer w0.635: SW704.5@20.9,1.75 v1(20.9,3.575) v1(20.9,4.325) ; v1(100.2,17.45) v1(100.875,17.45) v1(101.55,17.45) 102.475,17.45 103.595,18.57 P101.2@104.57,18.57 ; P801.1@101.715,57.841 101.715,57.085 102.6,56.2 v1@102.6,51.35
  Signal Layer 3 w0.3: v1(41.177,25.676) v1@41.225,25.628
  Bottom Layer w0.635: TP703.1@28.9,4.7 29.512,4.7 J101.1@30.95,3.262
  other v1: 102.6,51.325
VMCU_BUF: C625.1 C861.1 C863.1 C865.1 C867.1 R630.2 R675.2 U806.2 U860.6 U861.6 U862.6 U863.6 | length 71
  Top Layer w0.2: U860.6@53.5,44.65 53.663,44.488 53.716,44.488 54.075,44.129 C863.1@54.075,44.05 ; C861.1@58.05,39.45 U862.6@58.7,39.45 ; v1(63.2,35.3) 63.525,35.3 63.775,35.05 U863.6@63.95,35.05 63.95,35.45 63.725,35.675 C867.1@63.725,36.025 ; C865.1@63.25,41.175 63.825,41.175 U861.6@63.85,41.15
  Top Layer w0.3: C863.1@54.075,44.05 54.45,43.675 v1(54.5,43.675) ; v1@57.7,39.45 C861.1@58.05,39.45 ; v1(62.675,41.55) 63.025,41.2 63.25,41.2 C865.1@63.25,41.175 ; U806.2@68.5,36.7 68.5,36.85 68.675,37.025 69.25,37.025 69.725,37.5 v1(69.875,37.5)
  Top Layer w0.5: R630.2@52.15,29.2 v1(52.625,29.2) 53.05,29.625 53.875,29.625 C625.1@54.9,28.6 R675.2@54.9,27.55
  Signal Layer 3 w0.3: v1(54.5,43.675) 56.725,41.45 56.725,40.275 57.448,39.552 v1(57.553,39.552) ; v1(61.85,28.6) 61.85,28.525 61.5,28.875 61.5,29.525 62.25,30.275 62.25,31.503 62.147,31.606 62.147,34.247 v1(63.2,35.3) ; v1(69.1,29.3) 68.7,29.7 68.7,32.7 69.05,33.05 69.05,33.875 68.55,34.375 68.55,34.9 69.875,36.225 v1(69.875,37.5)
  Signal Layer 4 w0.3: v1(61.85,28.6) 63.125,28.6 63.775,27.95 67.75,27.95 v1(69.1,29.3)
  Signal Layer 4 w0.5: v1(52.625,29.2) 54.625,29.2 55.5,30.075 v1@56.525,30.075 ; v1(56.55,30.075) 58.234,30.075 58.809,29.5 60.982,29.5 60.982,29.454 61.837,28.6 v1(61.85,28.6)
  Bottom Layer w0.3: 56.4,39.1 56.4,38.8 ; v1(56.55,30.075) 56.425,30.075 54.9,31.6 54.9,32.7 55.657,33.457 55.657,34.443 55.3,34.8 55.3,35.5 56.4,36.6 56.4,38.8 ; 56.852,39.552 56.855,39.552 ; v1(62.675,41.55) 60.45,41.55 58.725,39.825 58.196,39.825 57.923,39.552 v1(57.553,39.552) 56.855,39.552 ; 56.4,38.8 56.407,38.807 56.407,39.104 56.855,39.552
VMCU_R: C761.1 C762.1 Q705.1 R701.1 R702.2 R709.2 TP700.1 U701.1 U701.4 | length 26.9
  Top Layer w0.1: R709.2@39.15,32.6 38.625,32.075 38.625,31.4 38.925,31.1 R701.1@39.975,31.1
  Top Layer w0.25: v1(38.625,29.1) 38.675,29.05 U701.4@39.15,29.05 ; U701.1@40.65,29.05 40.65,28.975 41.075,28.55 v1(41.075,28.475)
  Top Layer w0.3: v1(38.875,24.725) 39.125,24.975 R702.2@39.125,25.25
  Top Layer w0.5: C762.1@37,29.625 37.825,29.625 C761.1@37.9,29.55 ; R701.1@39.975,31.1 39.975,30.825 39.46,30.31 39.285,30.31 v1(38.65,29.675) ; C761.1@37.9,29.55 38.338,29.113 ; C761.1@37.9,29.55 38.025,29.675 38.338,29.675 ; 38.338,29.113 38.338,29.675 ; 38.338,29.113 38.35,29.1 v1(38.625,29.1) 38.65,29.125 v1(38.65,29.675) ; 38.338,29.675 v1(38.65,29.675) ; v1@34.175,28.65 v1(34.575,28.25) 34.7,28.375 Q705.1@34.7,28.888 34.263,28.888 v1(34.175,28.8) v1@34.175,28.65
  Signal Layer 4 w0.635: v1(34.175,28.8) 34.5,28.8 34.575,28.725 ; v1(34.575,28.25) 34.575,28.725 ; v1(41.075,28.475) 41.019,28.475 40.608,28.885 38.84,28.885 v1(38.625,29.1) 38.625,29.65 v1(38.65,29.675) 35.525,29.675 34.575,28.725
  Bottom Layer w0.3: v1(38.875,24.725) 38.875,25.3 41.075,27.5 v1(41.075,28.475)
  Bottom Layer w0.5: TP700.1@37.85,29.45 38.075,29.675 v1(38.65,29.675)
VMCU_S: C700.1 C701.1 Q705.4 R701.2 R710.2 R760.2 TP701.1 TP705.1 U702.2 U702.4 U702.9 U702.10 | length 25.1
  Top Layer w0.1: R701.2@37.125,31.1 38.125,31.1 38.425,31.4 38.425,32.125 R710.2@37.95,32.6
  Top Layer w0.2: U702.10@41.815,33.675 42.5,33.675 v1(42.602,33.777) ; U702.9@41.815,34.075 42.25,34.075 v1@42.475,33.85 ; U702.2@43.585,33.275 43.2,33.275 42.698,33.777 v1(42.602,33.777) ; U702.4@43.585,34.075 43.175,34.075 43,33.9 42.725,33.9 v1(42.602,33.777)
  Top Layer w0.3: v1(33.825,31.875) 33.925,31.975 R760.2@34.35,31.975
  Top Layer w0.5: R760.2@34.35,31.975 35.375,31.975 C700.1@35.8,31.55 ; v1@36.356,32.244 v1(36.356,32.231) 36.356,32.106 C700.1@35.8,31.55 ; R701.2@37.125,31.1 36.738,30.713 Q705.4@36,30.713 36,31.35 C700.1@35.8,31.55
  Signal Layer 4 w0.635: v1(33.825,31.875) 34.075,32.125 36.25,32.125 v1(36.356,32.231) 37.036,31.55 42.175,31.55 42.775,32.15 42.775,33.604 v1(42.602,33.777)
  Bottom Layer w0.2: TP705.1@41.75,33.775 42.6,33.775 v1(42.602,33.777)
  Bottom Layer w0.3: v1(33.825,31.875) 34.45,32.5 TP701.1@34.475,32.5
VMCU_SENSE: C632.1 R630.1 R631.2 TP708.1 U910.6 | length 4.7
  Top Layer w0.1: v1(49.575,31.1) 49.65,31.025 U910.6@50.625,31.025 50.65,31 51.05,31 C632.1@51.05,29.775 51.075,29.8 R631.2@51.6,29.8 R630.1@52.15,29.8
  Bottom Layer w0.1: TP708.1@48.875,31.575 49.1,31.575 v1(49.575,31.1)
VTARGET: R629.2 R691.1 U800.1 U806.1 | length 36.8
  Top Layer w0.3: v1(57.075,33.875) 57.6,33.875 R691.1@57.75,34.025 ; v1(59.2,31.825) 59.375,32 R629.2@59.375,32.3 ; U806.1@68.95,35.75 68.95,35.975 69.175,36.2 v1(69.175,36.225) ; U800.1@68.95,44.75 68.95,45.275 v1(69.075,45.4)
  Signal Layer 3 w0.3: v1(69.075,45.4) 69.075,43.375 69.4,43.05 69.4,41.175 69.393,41.168 69.371,41.168 69.05,40.847 69.05,40.025 69.193,39.882 69.193,36.243 v1(69.175,36.225)
  Signal Layer 4 w0.3: 56.75,33.55 56.5,33.3 ; v1(57.075,33.875) 56.5,33.3 ; v1(70.5,30.4) 70.2,30.4 69.8,30 66.4,30 65.9,29.5 64.3,29.5 63.55,30.25 60.703,30.25 59.2,31.753 v1(59.2,31.825) 56.775,31.825 56.5,32.1 56.5,33.3
  Bottom Layer w0.3: v1(69.175,36.225) 68.575,35.625 68.575,33.765 68.593,33.747 68.593,33.307 70.5,31.4 v1(70.5,30.4)
VTARGET_BUF: C655.1 C806.1 L801.1 R636.2 R687.2 R801.2 R809.2 U808.23 U808.24 | length 83.5
  Top Layer w0.3: R636.2@47.2,29.2 47.2,29.025 47.725,28.5 v1(47.8,28.5) ; v1(56.15,33.95) 56.15,34.35 56.1,34.4 L801.1@56.2,34.5 56.425,34.725 R809.2@56.425,35.325 ; v1(60.375,48.05) 60.675,47.75 C806.1@60.775,47.75 60.75,47.725 U808.24@60.75,46.745 61.605,46.745 61.795,46.555 U808.23@61.795,46.2 ; R801.2@64.45,43.6 64.7,43.6 65.05,43.95 v1(65.125,43.95)
  Top Layer w0.5: v1(56,25.175) 56.1,25.275 C655.1@56.1,26.05 56.3,26.25 R687.2@56.3,27.1
  Signal Layer 3 w0.3: v1(47.8,28.5) 47.8,27.675 47.95,27.525 47.95,26.329 v1(48.427,25.851) ; v1(65.125,43.95) 65.35,44.175 65.35,48.125 v1(65.25,48.225) ; v1(67.875,25.6) 73.9,31.625 73.9,36.8 73.4,37.3 73.4,44.675 v1(73.475,44.75)
  Signal Layer 4 w0.3: v1@48.575,25.675 54.978,25.675 55.021,25.718 55.429,25.718 55.472,25.675 55.5,25.675 v1(56,25.175) 62.125,25.175 62.75,24.55 66.825,24.55 v1(67.875,25.6) ; v1(60.375,48.05) 60.825,47.6 62.025,47.6 62.65,48.225 v1(65.25,48.225) 69.175,48.225 72.65,44.75 v1(73.475,44.75)
  Bottom Layer w0.3: v1(56,25.175) 56.75,25.925 56.75,29 57.2,29.45 57.2,30.4 56.725,30.875 56.225,30.875 55.3,31.8 55.3,32.5 56.15,33.35 v1(56.15,33.95)
VTARGET_SENSE: C638.1 R636.1 R637.2 U910.5 | length 2.9
  Top Layer w0.1: C638.1@46.1,29.775 46.125,29.8 R637.2@46.65,29.8 ; U910.5@46.225,31.025 U910.5@46.65,31.025 ; U910.5@46.775,31.025 U910.5@46.65,31.025 ; R636.1@47.2,29.8 R637.2@46.65,29.8 ; R637.2@46.65,29.8 U910.5@46.65,31.025
VTREF: Q800.4 R816.2 TPJ817.1 U800.2 | length 56.8
  Top Layer w0.3: Q800.4@63.925,37.55 63.925,37.045 64.3,36.67 v1(64.3,36.5) ; U800.2@68.5,45.7 68.5,46.55 R816.2@68.55,46.6 v1(68.55,47.275)
  Signal Layer 3 w0.3: v1(63.8,46.9) 63.25,46.35 63.25,41.25 64.825,39.675 64.825,39.175 64.3,38.65 v1(64.3,36.5)
  Signal Layer 4 w0.3: v1(63.8,46.9) 64.175,47.275 v1(68.55,47.275) 71.7,44.125 97.175,44.125 v1(101.9,48.85)
  Bottom Layer w0.3: v1(101.9,48.85) 101.975,48.925 102.55,48.35 TPJ817.1@102.65,48.35
pads on no net: D101.3 D102.2 D103.2 D104.2 D105.2 D800.5 D801.1 D903.2 D903.4 D903.5 LCD1.15 LCD1.16 LCD1.17 LCD1.18 LCD1.19 LCD1.20 M2.1 M3.1 P101.M1 P101.M2 P601.25@1.8,56.82 P601.26@1.8,48.18 P601.27@6.25,56.525 P601.27@6.85,56.82 P601.28@6.25,48.475 P601.28@6.85,48.18 P601.A2 P601.A3 P601.A8 P601.A10 P601.A11 P601.B2 P601.B3 P601.B8 P601.B10 P601.B11 P601.M1 P601.M2 P800.7 P800.11 P800.13 P801.10 P801.12 P801.14 P801.16 P801.18 P801.20 P801.M1 P801.M2 RP800.2 RP800.7 U1.15 U102.3 U102.4 U102.7 U600.8 U701.8 U800.17 U802.17 U806.17 U808.8 U808.9 U808.10 U810.17 U900.B11 U900.G2 U900.H2 U900.J2 U900.L3 U900.L8 U900.L12 U900.M4 U900.M12 U900.N7 U900.N12 U901.9 U902.C1

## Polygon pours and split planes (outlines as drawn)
3V3 on Signal Layer 5 "3V3_L5" (solid, remove dead copper, pour order 4): 44.511,36.5 44.511,40.7 42.9,40.7 42.9,43.125 28.825,43.125 25.05,46.9 17.725,46.9 12.825,51.8 12.825,60 33,60 100.575,60 100.575,43 102.4,43 102.4,40.375 68.925,40.375 68.925,26.325 29.3,26.325 29.3,6.775 20.075,6.775 20.075,0 0,0 0,36.5
VMCU on Signal Layer 5 "VMCU_L5" (solid, remove dead copper, pour order 5): 20.375,0 20.375,6.425 29.725,6.425 29.725,26 69.3,26 69.3,40 102.725,40 102.725,43.325 101.075,43.325 101.075,60 115,60 115,0
GND on Signal Layer 5 "GND_L5" (solid, remove dead copper, pour order 3): 44.25,36.875 44.25,40.5 42.65,40.5 42.65,42.85 28.8,42.85 24.95,46.7 17.575,46.7 12.6,51.675 12.6,55.6 12.6,60 0,60 0,46.25 0,36.875
GND on Top Layer "GND_L1" (solid, remove dead copper, pour order 2): 0,0 0,60 125,60 125,0
GND on Bottom Layer "GND_L6" (solid, remove dead copper, pour order 8): 0,0 0,60 125,60 125,0
GND on Signal Layer 2 "GND_L2" (solid, remove dead copper, pour order 9): 0,0 0,60 125,60 125,0
GND on Signal Layer 3 "GND_L3" (solid, remove dead copper, pour order 11): 0,0 0,60 125,60 125,0
GND on Signal Layer 4 "GND_L4" (solid, remove dead copper, pour order 12): 0.008,-0.345 0.008,59.655 125.008,59.655 125.008,-0.345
